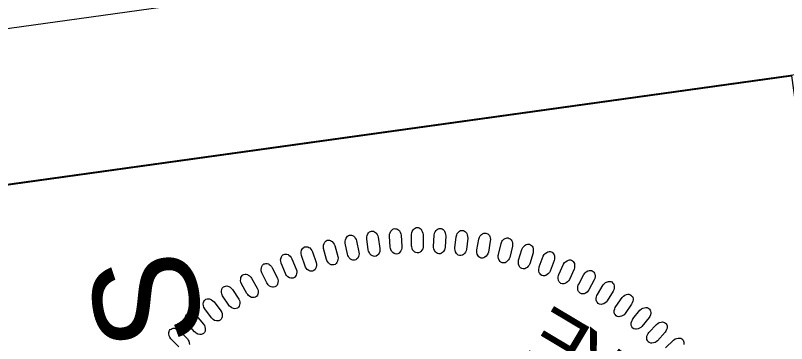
# Model space of a CAD drawing. Extents: x 477288 to 478604, y 497629 to 499448.
# Drawn here: x 477375.5 to 477460.3, y 499274.1 to 499310.2 of the extents above; entities that cross this region are included whole.
import ezdxf

# ---------------------------------------------------------------- set-up
doc = ezdxf.new("R2010")
doc.units = 0
for name, color, linetype in [('Sheet PE Seal Cell', 7, 'Continuous'), ('Sheet Plan CELL', 7, 'Continuous'), ('Sheet Plot Border Outside CELL', 7, 'Continuous'), ('Sheet Sticker Incomplete CELL', 7, 'Continuous')]:
    doc.layers.add(name, color=color, linetype=linetype)

msp = doc.modelspace()

# ---------------------------------------------------------------- linework, layer by layer
at = {"layer": 'Sheet PE Seal Cell'}
for points in [[(477414.287, 499284.383), (477414.119, 499285.598), (477414.126, 499285.82), (477414.158, 499285.966), (477414.246, 499286.149), (477414.327, 499286.271), (477414.427, 499286.365), (477414.525, 499286.419), (477414.634, 499286.454), (477414.748, 499286.45), (477414.87, 499286.437), (477414.982, 499286.392), (477415.099, 499286.308), (477415.169, 499286.237), (477415.257, 499286.098), (477415.341, 499285.928), (477415.385, 499285.774), (477415.565, 499284.53), (477415.566, 499284.359), (477415.54, 499284.214), (477415.474, 499284.044), (477415.382, 499283.89), (477415.297, 499283.798), (477415.15, 499283.717), (477415.004, 499283.677), (477414.85, 499283.696), (477414.74, 499283.731), (477414.6, 499283.812), (477414.459, 499283.964), (477414.367, 499284.132), (477414.32, 499284.256)], [(477416.709, 499284.686), (477416.617, 499285.91), (477416.638, 499286.13), (477416.679, 499286.274), (477416.779, 499286.452), (477416.867, 499286.569), (477416.973, 499286.656), (477417.074, 499286.704), (477417.185, 499286.732), (477417.298, 499286.721), (477417.419, 499286.7), (477417.528, 499286.649), (477417.64, 499286.556), (477417.706, 499286.481), (477417.784, 499286.337), (477417.857, 499286.163), (477417.892, 499286.005), (477417.993, 499284.753), (477417.984, 499284.582), (477417.949, 499284.439), (477417.872, 499284.274), (477417.77, 499284.127), (477417.68, 499284.039), (477417.528, 499283.968), (477417.38, 499283.937), (477417.228, 499283.965), (477417.12, 499284.007), (477416.986, 499284.097), (477416.854, 499284.257), (477416.773, 499284.432), (477416.734, 499284.558)], [(477419.049, 499284.844), (477419.035, 499286.071), (477419.069, 499286.29), (477419.12, 499286.431), (477419.23, 499286.602), (477419.326, 499286.713), (477419.437, 499286.793), (477419.54, 499286.835), (477419.653, 499286.856), (477419.765, 499286.838), (477419.885, 499286.809), (477419.99, 499286.751), (477420.096, 499286.652), (477420.157, 499286.574), (477420.226, 499286.424), (477420.288, 499286.246), (477420.313, 499286.086), (477420.335, 499284.83), (477420.315, 499284.66), (477420.272, 499284.52), (477420.184, 499284.359), (477420.074, 499284.218), (477419.978, 499284.137), (477419.821, 499284.076), (477419.672, 499284.054), (477419.522, 499284.092), (477419.417, 499284.14), (477419.288, 499284.238), (477419.167, 499284.407), (477419.097, 499284.585), (477419.066, 499284.715)], [(477421.468, 499284.78), (477421.531, 499286.005), (477421.579, 499286.222), (477421.638, 499286.359), (477421.759, 499286.523), (477421.862, 499286.627), (477421.977, 499286.702), (477422.084, 499286.736), (477422.197, 499286.75), (477422.308, 499286.725), (477422.426, 499286.689), (477422.527, 499286.624), (477422.627, 499286.518), (477422.683, 499286.436), (477422.742, 499286.283), (477422.793, 499286.101), (477422.807, 499285.941), (477422.751, 499284.685), (477422.72, 499284.517), (477422.668, 499284.38), (477422.57, 499284.225), (477422.452, 499284.091), (477422.351, 499284.016), (477422.191, 499283.964), (477422.04, 499283.952), (477421.893, 499284), (477421.791, 499284.055), (477421.669, 499284.16), (477421.559, 499284.336), (477421.5, 499284.519), (477421.478, 499284.65)], [(477423.812, 499284.62), (477423.951, 499285.839), (477424.013, 499286.053), (477424.08, 499286.186), (477424.211, 499286.342), (477424.32, 499286.439), (477424.441, 499286.506), (477424.549, 499286.534), (477424.663, 499286.541), (477424.772, 499286.509), (477424.888, 499286.465), (477424.985, 499286.394), (477425.077, 499286.283), (477425.128, 499286.197), (477425.178, 499286.04), (477425.217, 499285.856), (477425.221, 499285.695), (477425.086, 499284.445), (477425.045, 499284.279), (477424.984, 499284.145), (477424.878, 499283.997), (477424.75, 499283.871), (477424.645, 499283.803), (477424.482, 499283.761), (477424.331, 499283.758), (477424.187, 499283.815), (477424.089, 499283.876), (477423.973, 499283.989), (477423.874, 499284.171), (477423.827, 499284.358), (477423.813, 499284.489)], [(477412, 499283.914), (477411.755, 499285.116), (477411.749, 499285.338), (477411.771, 499285.485), (477411.847, 499285.674), (477411.921, 499285.801), (477412.015, 499285.901), (477412.109, 499285.961), (477412.215, 499286.003), (477412.329, 499286.006), (477412.452, 499286.001), (477412.567, 499285.963), (477412.689, 499285.886), (477412.764, 499285.82), (477412.86, 499285.687), (477412.954, 499285.522), (477413.008, 499285.371), (477413.266, 499284.141), (477413.277, 499283.97), (477413.261, 499283.824), (477413.205, 499283.65), (477413.123, 499283.491), (477413.044, 499283.393), (477412.902, 499283.303), (477412.759, 499283.254), (477412.605, 499283.263), (477412.492, 499283.291), (477412.348, 499283.364), (477412.197, 499283.506), (477412.095, 499283.669), (477412.04, 499283.79)], [(477426.235, 499284.379), (477426.45, 499285.587), (477426.526, 499285.797), (477426.601, 499285.925), (477426.742, 499286.072), (477426.856, 499286.163), (477426.981, 499286.222), (477427.091, 499286.243), (477427.204, 499286.243), (477427.311, 499286.204), (477427.424, 499286.153), (477427.517, 499286.076), (477427.602, 499285.959), (477427.647, 499285.87), (477427.687, 499285.711), (477427.714, 499285.524), (477427.709, 499285.363), (477427.496, 499284.125), (477427.443, 499283.962), (477427.375, 499283.832), (477427.259, 499283.691), (477427.124, 499283.573), (477427.015, 499283.511), (477426.849, 499283.48), (477426.698, 499283.487), (477426.559, 499283.552), (477426.464, 499283.62), (477426.356, 499283.74), (477426.269, 499283.928), (477426.234, 499284.117), (477426.227, 499284.249)], [(477428.602, 499283.9), (477428.892, 499285.092), (477428.981, 499285.296), (477429.064, 499285.419), (477429.214, 499285.558), (477429.334, 499285.641), (477429.462, 499285.692), (477429.573, 499285.706), (477429.687, 499285.699), (477429.791, 499285.653), (477429.9, 499285.595), (477429.987, 499285.513), (477430.066, 499285.391), (477430.105, 499285.299), (477430.135, 499285.138), (477430.15, 499284.949), (477430.134, 499284.789), (477429.844, 499283.566), (477429.782, 499283.407), (477429.705, 499283.282), (477429.58, 499283.148), (477429.439, 499283.039), (477429.325, 499282.984), (477429.158, 499282.963), (477429.009, 499282.979), (477428.873, 499283.054), (477428.783, 499283.127), (477428.683, 499283.254), (477428.607, 499283.447), (477428.584, 499283.638), (477428.586, 499283.77)], [(477407.33, 499282.616), (477406.937, 499283.778), (477406.902, 499283.998), (477406.906, 499284.147), (477406.958, 499284.343), (477407.015, 499284.478), (477407.096, 499284.591), (477407.182, 499284.661), (477407.282, 499284.716), (477407.394, 499284.733), (477407.518, 499284.743), (477407.635, 499284.72), (477407.767, 499284.659), (477407.849, 499284.603), (477407.961, 499284.482), (477408.075, 499284.332), (477408.147, 499284.188), (477408.558, 499283), (477408.59, 499282.832), (477408.593, 499282.686), (477408.559, 499282.506), (477408.497, 499282.338), (477408.431, 499282.231), (477408.301, 499282.123), (477408.166, 499282.057), (477408.012, 499282.047), (477407.897, 499282.06), (477407.744, 499282.114), (477407.577, 499282.236), (477407.455, 499282.385), (477407.386, 499282.498)], [(477409.691, 499283.347), (477409.372, 499284.531), (477409.351, 499284.752), (477409.364, 499284.901), (477409.428, 499285.094), (477409.494, 499285.225), (477409.581, 499285.331), (477409.671, 499285.397), (477409.775, 499285.445), (477409.888, 499285.455), (477410.012, 499285.458), (477410.129, 499285.428), (477410.255, 499285.358), (477410.333, 499285.297), (477410.438, 499285.17), (477410.543, 499285.012), (477410.606, 499284.864), (477410.94, 499283.653), (477410.962, 499283.483), (477410.956, 499283.336), (477410.911, 499283.16), (477410.839, 499282.995), (477410.766, 499282.893), (477410.63, 499282.794), (477410.49, 499282.736), (477410.336, 499282.736), (477410.222, 499282.757), (477410.073, 499282.82), (477409.914, 499282.952), (477409.802, 499283.108), (477409.74, 499283.226)], [(477430.826, 499283.278), (477431.191, 499284.449), (477431.292, 499284.648), (477431.383, 499284.766), (477431.541, 499284.894), (477431.666, 499284.97), (477431.797, 499285.013), (477431.909, 499285.02), (477432.022, 499285.005), (477432.123, 499284.953), (477432.228, 499284.889), (477432.31, 499284.801), (477432.38, 499284.674), (477432.414, 499284.58), (477432.434, 499284.418), (477432.437, 499284.229), (477432.411, 499284.07), (477432.045, 499282.868), (477431.973, 499282.712), (477431.888, 499282.592), (477431.756, 499282.467), (477431.607, 499282.367), (477431.491, 499282.319), (477431.323, 499282.309), (477431.174, 499282.334), (477431.044, 499282.417), (477430.958, 499282.496), (477430.866, 499282.629), (477430.803, 499282.826), (477430.792, 499283.018), (477430.802, 499283.15)], [(477405.167, 499281.801), (477404.703, 499282.936), (477404.654, 499283.152), (477404.648, 499283.301), (477404.688, 499283.501), (477404.736, 499283.64), (477404.81, 499283.756), (477404.891, 499283.832), (477404.988, 499283.893), (477405.099, 499283.918), (477405.221, 499283.935), (477405.34, 499283.92), (477405.475, 499283.867), (477405.561, 499283.816), (477405.68, 499283.703), (477405.804, 499283.559), (477405.885, 499283.421), (477406.368, 499282.261), (477406.412, 499282.096), (477406.423, 499281.949), (477406.401, 499281.768), (477406.351, 499281.596), (477406.291, 499281.485), (477406.168, 499281.37), (477406.037, 499281.295), (477405.884, 499281.276), (477405.769, 499281.282), (477405.613, 499281.326), (477405.438, 499281.437), (477405.308, 499281.578), (477405.231, 499281.687)], [(477433.098, 499282.536), (477433.536, 499283.682), (477433.649, 499283.873), (477433.747, 499283.985), (477433.913, 499284.104), (477434.043, 499284.172), (477434.176, 499284.206), (477434.288, 499284.206), (477434.4, 499284.184), (477434.498, 499284.126), (477434.598, 499284.055), (477434.674, 499283.963), (477434.737, 499283.832), (477434.765, 499283.736), (477434.774, 499283.572), (477434.765, 499283.383), (477434.73, 499283.226), (477434.289, 499282.049), (477434.208, 499281.899), (477434.116, 499281.784), (477433.975, 499281.668), (477433.82, 499281.577), (477433.701, 499281.537), (477433.533, 499281.537), (477433.386, 499281.572), (477433.261, 499281.662), (477433.181, 499281.747), (477433.098, 499281.885), (477433.046, 499282.085), (477433.048, 499282.278), (477433.066, 499282.409)], [(477435.248, 499281.687), (477435.756, 499282.804), (477435.881, 499282.987), (477435.986, 499283.093), (477436.159, 499283.201), (477436.293, 499283.26), (477436.428, 499283.287), (477436.54, 499283.279), (477436.65, 499283.25), (477436.743, 499283.186), (477436.84, 499283.109), (477436.911, 499283.012), (477436.964, 499282.877), (477436.986, 499282.78), (477436.985, 499282.616), (477436.965, 499282.428), (477436.92, 499282.273), (477436.405, 499281.126), (477436.314, 499280.982), (477436.215, 499280.873), (477436.068, 499280.766), (477435.908, 499280.684), (477435.787, 499280.652), (477435.619, 499280.663), (477435.474, 499280.707), (477435.355, 499280.805), (477435.28, 499280.894), (477435.206, 499281.037), (477435.168, 499281.241), (477435.18, 499281.433), (477435.207, 499281.563)], [(477403.118, 499280.763), (477402.582, 499281.867), (477402.52, 499282.081), (477402.505, 499282.229), (477402.533, 499282.43), (477402.572, 499282.572), (477402.638, 499282.693), (477402.714, 499282.774), (477402.807, 499282.841), (477402.916, 499282.872), (477403.037, 499282.897), (477403.157, 499282.889), (477403.295, 499282.845), (477403.384, 499282.8), (477403.51, 499282.694), (477403.642, 499282.559), (477403.732, 499282.425), (477404.288, 499281.298), (477404.341, 499281.136), (477404.361, 499280.991), (477404.351, 499280.808), (477404.311, 499280.634), (477404.258, 499280.519), (477404.144, 499280.396), (477404.018, 499280.314), (477403.866, 499280.284), (477403.75, 499280.283), (477403.592, 499280.317), (477403.411, 499280.417), (477403.271, 499280.55), (477403.188, 499280.653)], [(477400.946, 499279.578), (477400.342, 499280.646), (477400.267, 499280.856), (477400.243, 499281.002), (477400.257, 499281.205), (477400.288, 499281.349), (477400.346, 499281.473), (477400.418, 499281.56), (477400.506, 499281.633), (477400.613, 499281.67), (477400.732, 499281.703), (477400.852, 499281.703), (477400.993, 499281.667), (477401.084, 499281.628), (477401.216, 499281.53), (477401.357, 499281.404), (477401.454, 499281.276), (477402.08, 499280.186), (477402.144, 499280.027), (477402.174, 499279.883), (477402.174, 499279.7), (477402.146, 499279.524), (477402.1, 499279.406), (477401.993, 499279.277), (477401.872, 499279.186), (477401.723, 499279.147), (477401.607, 499279.139), (477401.447, 499279.163), (477401.26, 499279.252), (477401.113, 499279.375), (477401.023, 499279.473)], [(477437.431, 499280.617), (477438.009, 499281.699), (477438.146, 499281.875), (477438.257, 499281.974), (477438.436, 499282.071), (477438.573, 499282.121), (477438.711, 499282.139), (477438.821, 499282.125), (477438.929, 499282.09), (477439.019, 499282.019), (477439.111, 499281.936), (477439.174, 499281.835), (477439.219, 499281.697), (477439.235, 499281.599), (477439.224, 499281.435), (477439.192, 499281.248), (477439.137, 499281.097), (477438.552, 499279.985), (477438.452, 499279.846), (477438.347, 499279.744), (477438.193, 499279.646), (477438.028, 499279.575), (477437.905, 499279.551), (477437.737, 499279.572), (477437.597, 499279.625), (477437.484, 499279.73), (477437.415, 499279.823), (477437.349, 499279.971), (477437.323, 499280.177), (477437.349, 499280.368), (477437.384, 499280.495)], [(477439.488, 499279.485), (477440.132, 499280.529), (477440.279, 499280.695), (477440.396, 499280.787), (477440.582, 499280.873), (477440.722, 499280.915), (477440.859, 499280.924), (477440.969, 499280.902), (477441.075, 499280.86), (477441.159, 499280.784), (477441.246, 499280.696), (477441.303, 499280.591), (477441.34, 499280.45), (477441.349, 499280.351), (477441.327, 499280.189), (477441.284, 499280.005), (477441.22, 499279.857), (477440.566, 499278.784), (477440.457, 499278.651), (477440.346, 499278.556), (477440.186, 499278.468), (477440.018, 499278.407), (477439.892, 499278.391), (477439.727, 499278.422), (477439.59, 499278.485), (477439.484, 499278.597), (477439.421, 499278.694), (477439.365, 499278.845), (477439.352, 499279.052), (477439.389, 499279.241), (477439.432, 499279.367)], [(477398.941, 499278.311), (477398.271, 499279.338), (477398.182, 499279.542), (477398.149, 499279.688), (477398.151, 499279.891), (477398.173, 499280.036), (477398.223, 499280.164), (477398.289, 499280.255), (477398.372, 499280.333), (477398.477, 499280.377), (477398.593, 499280.417), (477398.713, 499280.425), (477398.856, 499280.398), (477398.949, 499280.364), (477399.088, 499280.275), (477399.235, 499280.157), (477399.341, 499280.036), (477400.034, 499278.987), (477400.107, 499278.833), (477400.146, 499278.692), (477400.158, 499278.51), (477400.141, 499278.331), (477400.103, 499278.211), (477400.004, 499278.075), (477399.89, 499277.977), (477399.743, 499277.928), (477399.628, 499277.913), (477399.467, 499277.927), (477399.274, 499278.004), (477399.12, 499278.118), (477399.024, 499278.21)], [(477397.03, 499276.927), (477396.297, 499277.91), (477396.196, 499278.109), (477396.154, 499278.251), (477396.142, 499278.454), (477396.155, 499278.6), (477396.198, 499278.731), (477396.258, 499278.826), (477396.335, 499278.909), (477396.437, 499278.96), (477396.551, 499279.007), (477396.67, 499279.022), (477396.814, 499279.005), (477396.91, 499278.977), (477397.053, 499278.897), (477397.208, 499278.788), (477397.322, 499278.674), (477398.079, 499277.671), (477398.162, 499277.522), (477398.21, 499277.383), (477398.233, 499277.201), (477398.227, 499277.023), (477398.197, 499276.9), (477398.106, 499276.759), (477397.998, 499276.653), (477397.855, 499276.596), (477397.741, 499276.573), (477397.579, 499276.577), (477397.382, 499276.642), (477397.221, 499276.746), (477397.119, 499276.832)], [(477441.501, 499278.155), (477442.21, 499279.157), (477442.367, 499279.314), (477442.491, 499279.398), (477442.68, 499279.472), (477442.823, 499279.505), (477442.961, 499279.505), (477443.069, 499279.477), (477443.172, 499279.428), (477443.252, 499279.348), (477443.332, 499279.253), (477443.383, 499279.145), (477443.411, 499279.003), (477443.414, 499278.903), (477443.382, 499278.742), (477443.327, 499278.561), (477443.253, 499278.418), (477442.533, 499277.388), (477442.417, 499277.263), (477442.299, 499277.175), (477442.134, 499277.096), (477441.963, 499277.047), (477441.837, 499277.038), (477441.674, 499277.079), (477441.541, 499277.15), (477441.442, 499277.269), (477441.385, 499277.371), (477441.339, 499277.525), (477441.34, 499277.732), (477441.388, 499277.918), (477441.438, 499278.041)], [(477443.401, 499276.792), (477444.171, 499277.747), (477444.338, 499277.894), (477444.467, 499277.97), (477444.66, 499278.032), (477444.805, 499278.056), (477444.943, 499278.048), (477445.049, 499278.013), (477445.149, 499277.958), (477445.223, 499277.872), (477445.297, 499277.774), (477445.342, 499277.662), (477445.36, 499277.518), (477445.357, 499277.418), (477445.315, 499277.26), (477445.249, 499277.082), (477445.166, 499276.945), (477444.383, 499275.962), (477444.259, 499275.844), (477444.136, 499275.763), (477443.967, 499275.695), (477443.792, 499275.657), (477443.666, 499275.657), (477443.506, 499275.708), (477443.377, 499275.787), (477443.286, 499275.911), (477443.236, 499276.016), (477443.199, 499276.173), (477443.213, 499276.38), (477443.273, 499276.563), (477443.331, 499276.682)], [(477395.174, 499275.395), (477394.38, 499276.33), (477394.267, 499276.522), (477394.216, 499276.662), (477394.192, 499276.864), (477394.195, 499277.011), (477394.229, 499277.144), (477394.283, 499277.242), (477394.356, 499277.33), (477394.454, 499277.387), (477394.565, 499277.442), (477394.683, 499277.464), (477394.828, 499277.455), (477394.925, 499277.434), (477395.073, 499277.362), (477395.235, 499277.264), (477395.355, 499277.158), (477396.174, 499276.204), (477396.266, 499276.06), (477396.322, 499275.925), (477396.357, 499275.745), (477396.362, 499275.566), (477396.339, 499275.442), (477396.258, 499275.295), (477396.157, 499275.183), (477396.017, 499275.117), (477395.905, 499275.087), (477395.743, 499275.081), (477395.543, 499275.133), (477395.375, 499275.227), (477395.269, 499275.306)], [(477445.155, 499275.287), (477445.984, 499276.192), (477446.159, 499276.328), (477446.292, 499276.396), (477446.489, 499276.445), (477446.635, 499276.46), (477446.772, 499276.443), (477446.876, 499276.402), (477446.972, 499276.341), (477447.04, 499276.251), (477447.109, 499276.147), (477447.145, 499276.033), (477447.155, 499275.889), (477447.146, 499275.79), (477447.094, 499275.634), (477447.017, 499275.461), (477446.926, 499275.328), (477446.083, 499274.397), (477445.951, 499274.287), (477445.824, 499274.215), (477445.65, 499274.157), (477445.473, 499274.13), (477445.347, 499274.137), (477445.192, 499274.198), (477445.067, 499274.285), (477444.985, 499274.415), (477444.941, 499274.523), (477444.914, 499274.682), (477444.941, 499274.888), (477445.013, 499275.066), (477445.078, 499275.182)]]:
    msp.add_lwpolyline(points, close=True, dxfattribs=at)
for points in [[(477393.439, 499273.739), (477392.589, 499274.624), (477392.464, 499274.807), (477392.404, 499274.944), (477392.367, 499275.145), (477392.362, 499275.291), (477392.387, 499275.426), (477392.435, 499275.527), (477392.502, 499275.62), (477392.597, 499275.683), (477392.703, 499275.744), (477392.82, 499275.774), (477392.965, 499275.774), (477393.063, 499275.758), (477393.216, 499275.697), (477393.383, 499275.609), (477393.51, 499275.51), (477394.387, 499274.61), (477394.487, 499274.472), (477394.553, 499274.34), (477394.598, 499274.163), (477394.614, 499273.985)], [(477446.968, 499273.615), (477447.852, 499274.465), (477448.036, 499274.59), (477448.172, 499274.65), (477448.372, 499274.687), (477448.519, 499274.692), (477448.655, 499274.667), (477448.756, 499274.619), (477448.848, 499274.552), (477448.911, 499274.458), (477448.972, 499274.351), (477449.003, 499274.234), (477449.002, 499274.089), (477448.987, 499273.991)]]:
    msp.add_lwpolyline(points, dxfattribs=at)
at = {"layer": 'Sheet Plan CELL'}
for points in [[(477312.184, 499282.891), (477518.944, 497797.172), (478558.922, 497941.9), (478352.165, 499427.595)], [(477363.175, 499188.999), (477349.381, 499288.03), (477460.818, 499303.551), (477474.614, 499204.507)]]:
    msp.add_lwpolyline(points, close=True, dxfattribs=at)
at = {"layer": 'Sheet Plot Border Outside CELL'}
msp.add_lwpolyline([(478604.168, 497780.105), (478372.12, 499447.536), (477287.571, 499296.605), (477519.619, 497629.174)], close=True, dxfattribs=at)

# ---------------------------------------------------------------- texts
at = {"layer": 'Sheet PE Seal Cell'}
for s, rotation, p in [('E', 149.19094, (477439.189, 499275.546)), ('K', 142.34528, (477443, 499272.638))]:
    msp.add_text(s, height=6.236, rotation=rotation, dxfattribs=at).set_placement(p)
at = {"layer": 'Sheet Sticker Incomplete CELL'}
msp.add_text('INCOMPLETE PLANS', height=11.52, rotation=97.92268, dxfattribs=at).set_placement((477416.197, 499131.205))

doc.saveas('drawing.dxf')
